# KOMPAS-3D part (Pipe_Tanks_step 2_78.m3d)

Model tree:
1. X Axis
2. Y Axis
3. Z Axis  (labels: Bend 90 Dn 50; Pipe Dn 50)
     Òîëùèíà ñòåíêè 1 = 1

Referenced files in C:\Documents and Settings\kashirsky\Мои документы\Camtasia Studio\Pipelines3D\Tanks\: Tanks_step 2.a3d
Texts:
  Pipe Dn 50
  Steel ASTM A295
  Three Point Plane
  Plane at Angle
  Line and Point Plane
  Axis through Two Vertices
  Axis of Feature
  Axis of Conical Surface
  Axis through Edge
  Trim by Surface
  Trim by Sketch
  Feature with No History
  Intersection Axis of Two Planes
  Two Line Plane
  Line and Face Plane
  Bend by line
  Hole in sheet body
  Cut in sheet body
  Point in CM
  Linear Dimension from Line to Point
  Surface Finish Symbol
  Geometric Tolerance Symbol
  Leader #1
  Leader #2
  Leader #3
  Shape Deviations and Datum
  Node point number
  Mark of coordination axis
  Node point designation
  Mark/Reference designation with leader
  Mark/reference designation on line
  Mark/Reference designation without leader
  Bend 90 Dn 50
  Plane of section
